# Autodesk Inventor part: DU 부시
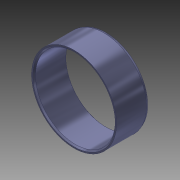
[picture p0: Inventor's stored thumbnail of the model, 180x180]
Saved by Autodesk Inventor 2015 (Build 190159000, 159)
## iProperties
Created: 2023-11
Part Number: DU 부시
Material: 강철, 합금
Document SubType Name: Modeling
Designer: mdu-01
Density: 1 g/cm^3
Appearance: 반광택(1)
Author: mdu-01
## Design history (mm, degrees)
sketch "스케치1"
  geometry: L1 (0, 0)-(0, -30); L2 (38.75, 0)-(40, 0); L3 (40, 0)-(40, -28.125); L4 (39.318, -30)-(37.75, -30); L5 (37.5, -29.75)-(37.5, -1.25); L6 (38.75, 0)-(37.5, -1.25); L7 (40, -28.125)-(39.318, -30); L8 (37.75, -30)-(37.5, -29.75); 3 further points
  constraints: 16 end point, 8 point on line, 2 parallel, 1 horizontal, 1 perpendicular, 1 vertical
  dimensions: "d0" = 30 distance of L1.start L1.end; "d1" = 1.25 distance of L2.start point (37.5, 0); "d2" = 1.25 distance of L5.end point (37.5, 0) (= d1); "d3" = 1.875 distance of L3.end point (40, -30); "d4" = 20 deg angle of L3 L7; "d5" = 0.25 distance of L4.end point (37.5, -30); "d6" = 0.25 distance of L5.start point (37.5, -30) (= d5); "d7" = 75 diameter of L5 L1; "d8" = 80 diameter of L3 L1
revolve "회전1" sketch "스케치1" stored, may be unused: angle "d9" = 90 deg
node "솔리드1"
